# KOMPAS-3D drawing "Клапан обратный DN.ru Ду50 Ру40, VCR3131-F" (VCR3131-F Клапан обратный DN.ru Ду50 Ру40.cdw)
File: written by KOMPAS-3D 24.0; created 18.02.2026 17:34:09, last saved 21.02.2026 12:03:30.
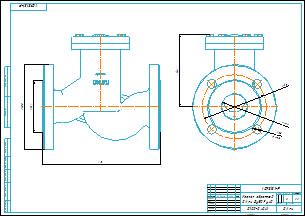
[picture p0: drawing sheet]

Document properties: art: D100-04041; Автор: R2D2; Форматы листов документа: A2; Полное имя файла: VCR3131-F Клапан обратный DN.ru Ду50 Ру40.m3d; Масса: 12; Наименование: Клапан обратный DN.ru Ду50 Ру40; Количество листов документа: 1; Примечание: D100-04041

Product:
- Part/product: Клапан обратный DN.ru Ду50 Ру40  | designation VCR3131-F
    Масса: 12
    Форматы листов документа: A2
    Примечание: D100-04041
    additional columns: D100-04041

Views: Вид 1, Спереди, Проекционный вид 2
Referenced files in E:\Работа\Зайцев\VCR3131-F Клапан обратный DN.ru Ду15-300\DN50\: VCR3131-F Клапан обратный DN.ru Ду50 Ру40.m3d
Referenced files in E:\Работа\Зайцев\Для компаса\: чертеж DN.ru А3.cdt
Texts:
  VCR3131-F
  чертеж DN.ru А3.cdt
  Клапан обратный
  DN.ru Ду50 Ру40
  prop
  Клапан обратный DN.ru Ду50 Ру40
  VCR3131-F Клапан обратный DN.ru Ду50 Ру40
Dimensions and other numbers on the sheet: 0; 3; 2; 4; 142; 125; 50; 18; 4 отв.; 230; 165; 102; 1:1; 1; 12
